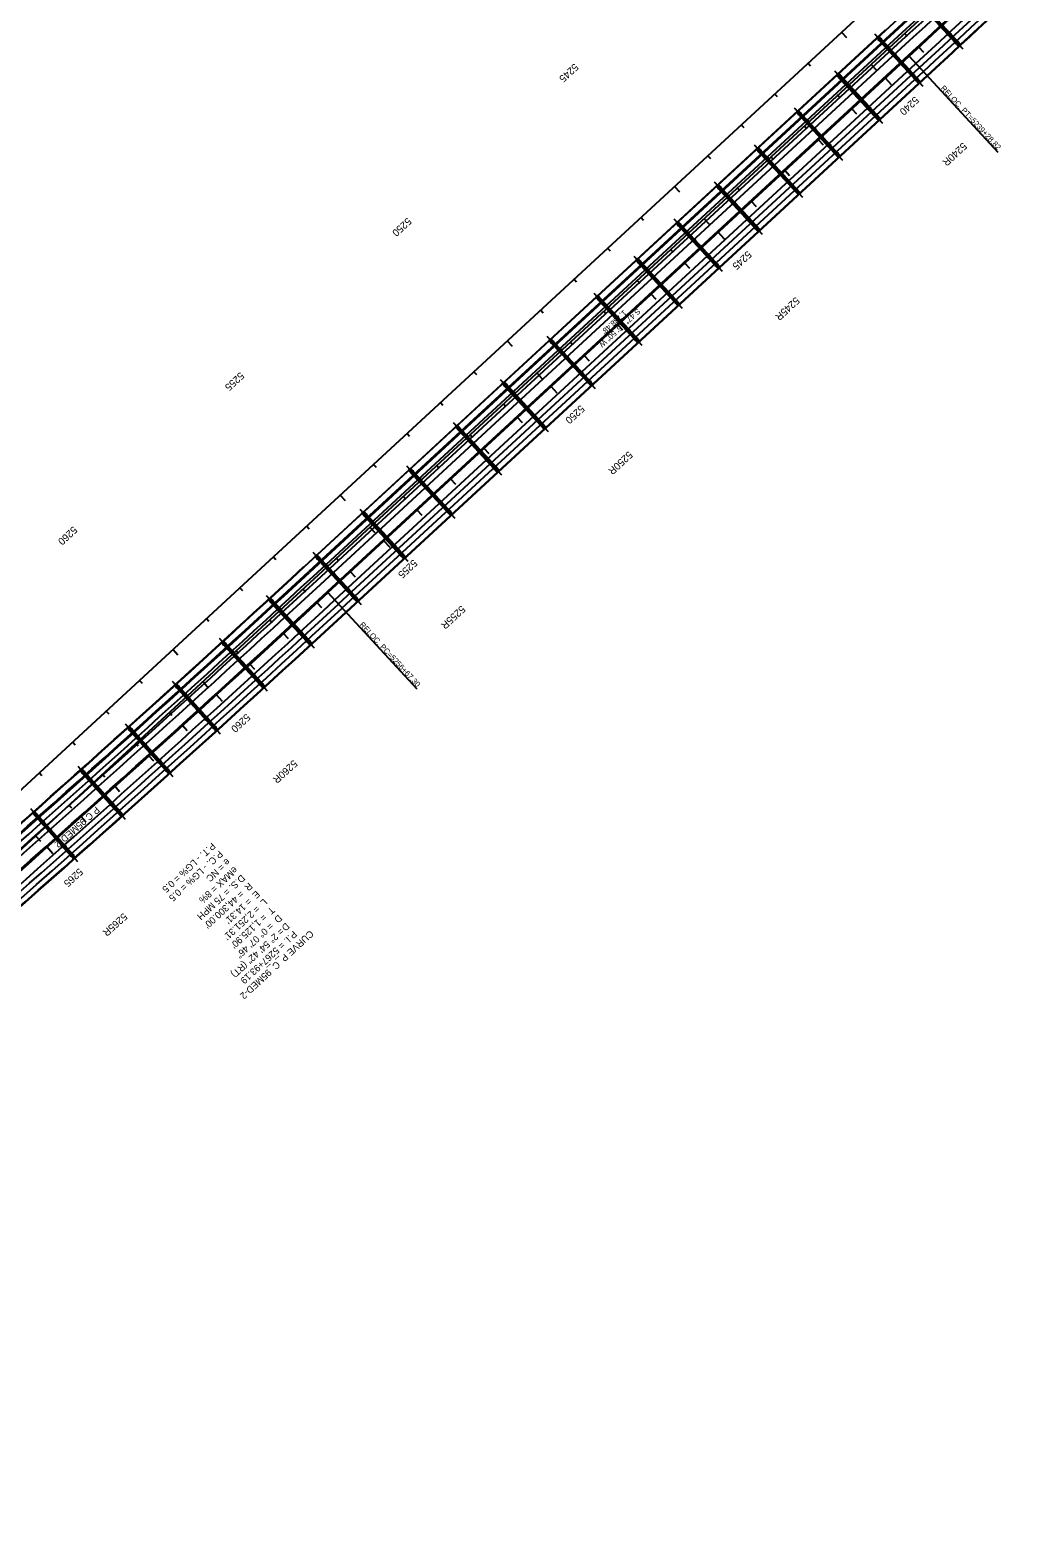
# Model space of a CAD drawing. Extents: x 2160877 to 2175861, y 601747 to 617724.
# Drawn here: x 2165397 to 2167565, y 605823 to 609138 of the extents above; entities that cross this region are included whole.
import ezdxf

# ---------------------------------------------------------------- set-up
doc = ezdxf.new("R2010")
doc.units = 0
for name, color, linetype in [('BR_CENTER LINES', 7, 'Continuous'), ('BR_CONCRETE', 7, 'Continuous'), ('RD_HC_Cl', 7, 'Continuous'), ('RD_HC_CL_Rel', 7, 'Continuous'), ('RD_HC_Data_Rel', 7, 'Continuous'), ('RD_HC_Data_Tic', 7, 'Continuous'), ('RD_HC_Data_Tic_Rel', 7, 'Continuous'), ('RD_HC_TX_Rel_Sta50', 7, 'Continuous'), ('RD_HC_TX_Rel_StaOther', 7, 'Continuous'), ('RD_HC_TX_StaOther', 7, 'Continuous'), ('RD_PD_Final_LnLine', 7, 'Continuous'), ('RD_PD_MedBWall', 7, 'Continuous')]:
    doc.layers.add(name, color=color, linetype=linetype)

msp = doc.modelspace()

# ---------------------------------------------------------------- linework, layer by layer
at = {"layer": 'BR_CENTER LINES'}
for p, q in [((2167340.3, 609210.9), (2167446.5, 609096.4)), ((2167252.3, 609129.6), (2167358.3, 609014.8)), ((2167164.1, 609048.2), (2167270.1, 608933.4)), ((2167076, 608966.8), (2167181.9, 608852)), ((2166987.8, 608885.3), (2167093.8, 608770.6)), ((2166899.7, 608803.9), (2167005.6, 608689.2)), ((2166811.5, 608722.5), (2166917.4, 608607.8)), ((2166723.3, 608641.1), (2166829.3, 608526.4)), ((2166635.2, 608559.7), (2166741.1, 608445)), ((2166532.3, 608464.7), (2166638.3, 608350)), ((2166429.5, 608369.8), (2166535.4, 608255)), ((2166326.6, 608274.8), (2166432.6, 608160)), ((2166223.8, 608179.8), (2166329.7, 608065.1)), ((2166120.9, 608084.8), (2166226.8, 607970.1)), ((2166018, 607989.8), (2166124, 607875.1)), ((2165915.2, 607895.1), (2166021, 607780.1)), ((2165812.2, 607800.7), (2165917.6, 607685.4)), ((2165708.9, 607706.6), (2165813.9, 607591)), ((2165605.3, 607612.9), (2165709.9, 607496.9)), ((2165501.3, 607519.5), (2165605.6, 607403.2)), ((2165397.1, 607426.4), (2165501, 607309.8))]:
    msp.add_line(p, q, dxfattribs=at)
at = {"layer": 'BR_CONCRETE'}
for p, q in [((2167275.8, 609137.6), (2165998.5, 607958.2)), ((2167285.9, 609126.6), (2166008.7, 607947.2)), ((2167287.5, 609124.9), (2166010.3, 607945.5)), ((2167326.9, 609082.3), (2166049.6, 607902.9)), ((2167328.4, 609080.5), (2166051.2, 607901.1)), ((2167367.8, 609037.9), (2166090.6, 607858.5)), ((2167368.5, 609037.2), (2166091.2, 607857.8)), ((2167368.6, 609037.1), (2166091.3, 607857.7))]:
    msp.add_line(p, q, dxfattribs=at)
for points in [[(2167349.1, 609205.5), (2167345.1, 609201.7), (2167437.7, 609101.8), (2167441.7, 609105.6)], [(2167261.1, 609124.1), (2167257.1, 609120.4), (2167349.5, 609020.3), (2167353.5, 609024.1)], [(2167173, 609042.7), (2167168.9, 609038.9), (2167261.3, 608938.9), (2167265.3, 608942.6)], [(2167084.8, 608961.3), (2167080.8, 608957.5), (2167173.1, 608857.5), (2167177.2, 608861.2)], [(2166996.6, 608879.9), (2166992.6, 608876.1), (2167085, 608776.1), (2167089, 608779.8)], [(2166908.5, 608798.5), (2166904.4, 608794.7), (2166996.8, 608694.7), (2167000.8, 608698.4)], [(2166820.3, 608717), (2166816.3, 608713.3), (2166908.6, 608613.3), (2166912.7, 608617)], [(2166732.1, 608635.6), (2166728.1, 608631.9), (2166820.5, 608531.9), (2166824.5, 608535.6)], [(2166644, 608554.2), (2166639.9, 608550.5), (2166732.3, 608450.5), (2166736.4, 608454.2)], [(2166541.1, 608459.2), (2166537.1, 608455.5), (2166629.5, 608355.5), (2166633.5, 608359.2)], [(2166438.3, 608364.3), (2166434.2, 608360.5), (2166526.6, 608260.5), (2166530.6, 608264.2)], [(2166335.4, 608269.3), (2166331.4, 608265.6), (2166423.8, 608165.5), (2166427.8, 608169.3)], [(2166232.6, 608174.3), (2166228.5, 608170.6), (2166320.9, 608070.5), (2166324.9, 608074.3)], [(2166129.7, 608079.3), (2166125.7, 608075.6), (2166218, 607975.6), (2166222.1, 607979.3)], [(2166026.8, 607984.4), (2166022.8, 607980.6), (2166115.2, 607880.6), (2166119.2, 607884.3)], [(2165924, 607889.6), (2165920, 607885.8), (2166012.2, 607785.6), (2166016.2, 607789.4)], [(2165821, 607795.1), (2165816.9, 607791.4), (2165908.8, 607690.9), (2165912.9, 607694.7)], [(2165717.6, 607701.1), (2165713.5, 607697.4), (2165805.1, 607596.6), (2165809.2, 607600.3)], [(2165614, 607607.3), (2165609.9, 607603.6), (2165701.1, 607502.5), (2165705.2, 607506.2)], [(2165510.1, 607513.9), (2165506, 607510.2), (2165596.9, 607408.8), (2165601, 607412.5)], [(2165405.8, 607420.8), (2165401.7, 607417.1), (2165492.3, 607315.4), (2165496.4, 607319.1)]]:
    msp.add_lwpolyline(points, close=True, dxfattribs=at)
for centre, radius in [((2167264.1, 609116.8), 3), ((2167264.1, 609116.8), 2), ((2167417, 609128.2), 3), ((2167417, 609128.2), 2), ((2167434, 609109.8), 3), ((2167434, 609109.8), 2), ((2167280, 609099.6), 3), ((2167280, 609099.6), 2), ((2167296, 609082.3), 3), ((2167296, 609082.3), 2), ((2167311.9, 609065), 3), ((2167311.9, 609065), 2), ((2167328.9, 609046.7), 3), ((2167328.9, 609046.7), 2), ((2167175.9, 609035.4), 3), ((2167175.9, 609035.4), 2), ((2167191.9, 609018.2), 3), ((2167191.9, 609018.2), 2), ((2167345.8, 609028.3), 3), ((2167345.8, 609028.3), 2), ((2167207.8, 609000.9), 3), ((2167207.8, 609000.9), 2), ((2167223.7, 608983.6), 3), ((2167223.7, 608983.6), 2), ((2167087.7, 608954), 3), ((2167087.7, 608954), 2), ((2167103.7, 608936.8), 3), ((2167240.7, 608965.3), 3), ((2167240.7, 608965.3), 2), ((2167257.7, 608946.9), 3), ((2167257.7, 608946.9), 2), ((2167103.7, 608936.8), 2), ((2167119.6, 608919.5), 3), ((2167119.6, 608919.5), 2), ((2166999.6, 608872.6), 3), ((2166999.6, 608872.6), 2), ((2167135.6, 608902.2), 3), ((2167135.6, 608902.2), 2), ((2167152.5, 608883.9), 3), ((2167152.5, 608883.9), 2), ((2167015.5, 608855.3), 3), ((2167015.5, 608855.3), 2), ((2167031.5, 608838.1), 3), ((2167169.5, 608865.5), 3), ((2167169.5, 608865.5), 2), ((2167031.5, 608838.1), 2), ((2167047.4, 608820.8), 3), ((2167047.4, 608820.8), 2), ((2166911.4, 608791.2), 3), ((2166911.4, 608791.2), 2), ((2166927.4, 608773.9), 3), ((2166927.4, 608773.9), 2), ((2167064.4, 608802.4), 3), ((2167064.4, 608802.4), 2), ((2167081.3, 608784.1), 3), ((2167081.3, 608784.1), 2), ((2166943.3, 608756.7), 3), ((2166943.3, 608756.7), 2), ((2166959.3, 608739.4), 3), ((2166959.3, 608739.4), 2), ((2166823.3, 608709.8), 3), ((2166823.3, 608709.8), 2), ((2166976.2, 608721), 3), ((2166976.2, 608721), 2), ((2166839.2, 608692.5), 3), ((2166839.2, 608692.5), 2), ((2166855.1, 608675.3), 3), ((2166855.1, 608675.3), 2), ((2166993.2, 608702.7), 3), ((2166993.2, 608702.7), 2), ((2166871.1, 608658), 3), ((2166871.1, 608658), 2), ((2166888, 608639.6), 3), ((2166888, 608639.6), 2), ((2166735.1, 608628.4), 3), ((2166735.1, 608628.4), 2), ((2166751, 608611.1), 3), ((2166751, 608611.1), 2), ((2166905, 608621.3), 3), ((2166905, 608621.3), 2), ((2166767, 608593.9), 3), ((2166767, 608593.9), 2), ((2166782.9, 608576.6), 3), ((2166782.9, 608576.6), 2), ((2166646.9, 608547), 3), ((2166646.9, 608547), 2), ((2166799.9, 608558.2), 3), ((2166799.9, 608558.2), 2), ((2166816.8, 608539.9), 3), ((2166662.9, 608529.7), 3), ((2166662.9, 608529.7), 2), ((2166678.8, 608512.4), 3), ((2166678.8, 608512.4), 2), ((2166816.8, 608539.9), 2), ((2166694.8, 608495.2), 3), ((2166694.8, 608495.2), 2), ((2166711.7, 608476.8), 3), ((2166711.7, 608476.8), 2), ((2166544.1, 608452), 3), ((2166544.1, 608452), 2), ((2166728.7, 608458.4), 3), ((2166728.7, 608458.4), 2), ((2166560, 608434.7), 3), ((2166560, 608434.7), 2), ((2166576, 608417.5), 3), ((2166576, 608417.5), 2), ((2166591.9, 608400.2), 3), ((2166591.9, 608400.2), 2), ((2166608.9, 608381.8), 3), ((2166608.9, 608381.8), 2), ((2166441.2, 608357), 3), ((2166441.2, 608357), 2), ((2166625.8, 608363.5), 3), ((2166625.8, 608363.5), 2), ((2166457.2, 608339.8), 3), ((2166457.2, 608339.8), 2), ((2166473.1, 608322.5), 3), ((2166473.1, 608322.5), 2), ((2166489.1, 608305.2), 3), ((2166489.1, 608305.2), 2), ((2166506, 608286.9), 3), ((2166506, 608286.9), 2), ((2166338.4, 608262), 3), ((2166338.4, 608262), 2), ((2166354.3, 608244.8), 3), ((2166354.3, 608244.8), 2), ((2166523, 608268.5), 3), ((2166523, 608268.5), 2), ((2166370.3, 608227.5), 3), ((2166370.3, 608227.5), 2), ((2166386.2, 608210.2), 3), ((2166386.2, 608210.2), 2), ((2166403.2, 608191.9), 3), ((2166403.2, 608191.9), 2), ((2166235.5, 608167.1), 3), ((2166235.5, 608167.1), 2), ((2166251.5, 608149.8), 3), ((2166251.5, 608149.8), 2), ((2166420.1, 608173.5), 3), ((2166420.1, 608173.5), 2), ((2166267.4, 608132.5), 3), ((2166267.4, 608132.5), 2), ((2166283.3, 608115.3), 3), ((2166283.3, 608115.3), 2), ((2166300.3, 608096.9), 3), ((2166300.3, 608096.9), 2), ((2166317.3, 608078.5), 3), ((2166317.3, 608078.5), 2), ((2166132.7, 608072.1), 3), ((2166132.7, 608072.1), 2), ((2166148.6, 608054.8), 3), ((2166148.6, 608054.8), 2), ((2166164.5, 608037.6), 3), ((2166164.5, 608037.6), 2), ((2166180.5, 608020.3), 3), ((2166180.5, 608020.3), 2), ((2166029.8, 607977.1), 3), ((2166029.8, 607977.1), 2), ((2166197.4, 608001.9), 3), ((2166197.4, 608001.9), 2), ((2166214.4, 607983.6), 3), ((2166214.4, 607983.6), 2), ((2166045.7, 607959.8), 3), ((2166045.7, 607959.8), 2), ((2166061.7, 607942.6), 3), ((2166061.7, 607942.6), 2), ((2166077.6, 607925.3), 3), ((2166077.6, 607925.3), 2), ((2165926.9, 607882.3), 3), ((2165926.9, 607882.3), 2), ((2166094.6, 607906.9), 3), ((2166094.6, 607906.9), 2), ((2166111.6, 607888.6), 3), ((2166111.6, 607888.6), 2), ((2165942.9, 607865), 3), ((2165942.9, 607865), 2), ((2165958.8, 607847.7), 3), ((2165958.8, 607847.7), 2), ((2165974.7, 607830.4), 3), ((2165974.7, 607830.4), 2), ((2165991.6, 607812), 3), ((2165991.6, 607812), 2), ((2165823.9, 607787.9), 3), ((2165823.9, 607787.9), 2), ((2166008.5, 607793.6), 3), ((2166008.5, 607793.6), 2), ((2165839.7, 607770.5), 3), ((2165839.7, 607770.5), 2), ((2165855.6, 607753.2), 3), ((2165855.6, 607753.2), 2), ((2165871.5, 607735.8), 3), ((2165871.5, 607735.8), 2), ((2165888.3, 607717.4), 3), ((2165888.3, 607717.4), 2), ((2165720.5, 607693.8), 3), ((2165720.5, 607693.8), 2), ((2165905.2, 607699), 3), ((2165905.2, 607699), 2), ((2165736.3, 607676.4), 3), ((2165736.3, 607676.4), 2), ((2165752.1, 607659), 3), ((2165752.1, 607659), 2), ((2165767.9, 607641.6), 3), ((2165767.9, 607641.6), 2), ((2165784.7, 607623.1), 3), ((2165784.7, 607623.1), 2), ((2165616.9, 607600), 3), ((2165616.9, 607600), 2), ((2165632.6, 607582.6), 3), ((2165632.6, 607582.6), 2), ((2165801.6, 607604.6), 3), ((2165801.6, 607604.6), 2), ((2165648.4, 607565.1), 3), ((2165648.4, 607565.1), 2), ((2165664.1, 607547.7), 3), ((2165664.1, 607547.7), 2), ((2165680.8, 607529.1), 3), ((2165680.8, 607529.1), 2), ((2165512.9, 607506.6), 3), ((2165512.9, 607506.6), 2), ((2165528.6, 607489.1), 3), ((2165528.6, 607489.1), 2), ((2165697.6, 607510.6), 3), ((2165697.6, 607510.6), 2), ((2165544.3, 607471.6), 3), ((2165544.3, 607471.6), 2), ((2165560, 607454.1), 3), ((2165560, 607454.1), 2), ((2165408.7, 607413.5), 3), ((2165408.7, 607413.5), 2), ((2165576.7, 607435.5), 3), ((2165576.7, 607435.5), 2), ((2165593.4, 607416.9), 3), ((2165593.4, 607416.9), 2), ((2165424.3, 607395.9), 3), ((2165424.3, 607395.9), 2), ((2165439.9, 607378.4), 3), ((2165439.9, 607378.4), 2), ((2165455.6, 607360.8), 3), ((2165455.6, 607360.8), 2), ((2165472.2, 607342.2), 3), ((2165472.2, 607342.2), 2), ((2165488.8, 607323.5), 3), ((2165488.8, 607323.5), 2)]:
    msp.add_circle(centre, radius, dxfattribs=at)
for centre, radius, start, end in [((2118143, 662346), 72438.5, 312.719474, 314.001576), ((2118143, 662346), 72440.8, 312.719474, 314.001576), ((2118143, 662346), 72498.8, 312.719474, 314.001574), ((2118143, 662346), 72501.2, 312.719474, 314.001574), ((2118143, 662346), 72559.2, 312.719474, 314.001572), ((2118143, 662346), 72560.2, 312.719474, 314.001572), ((2118143, 662346), 72560.3, 312.719474, 314.001572), ((2135996.9, 640448.5), 44223.5, 311.14908, 312.71947), ((2135996.9, 640448.5), 44238.5, 311.14908, 312.71947), ((2135996.9, 640448.5), 44240.8, 311.14908, 312.71947), ((2135996.9, 640448.5), 44298.8, 311.14908, 312.71947), ((2135996.9, 640448.5), 44301.2, 311.14908, 312.71947), ((2135996.9, 640448.5), 44359.2, 311.14907, 312.71947), ((2135996.9, 640448.5), 44360.2, 311.14907, 312.71947), ((2135996.9, 640448.5), 44360.3, 311.14907, 312.71947)]:
    msp.add_arc(centre, radius, start, end, dxfattribs=at)
at = {"layer": 'RD_HC_Cl'}
for p, q in [((2172207.3, 613775.1), (2163672.2, 605893.8)), ((2172272.5, 613704.6), (2163737.4, 605823.3))]:
    msp.add_line(p, q, dxfattribs=at)
at = {"layer": 'RD_HC_CL_Rel'}
msp.add_line((2167327.7, 609081.4), (2166050.4, 607902), dxfattribs=at)
for centre, radius, start, end in [((2118143, 662346), 72500, 312.719474, 314.517591), ((2135996.9, 640448.5), 44300, 309.80773, 312.71947)]:
    msp.add_arc(centre, radius, start, end, dxfattribs=at)
at = {"layer": 'RD_HC_Data_Rel'}
for p, q in [((2167327.7, 609081.4), (2167523.3, 608869.6)), ((2166050.4, 607902), (2166246.8, 607689.4))]:
    msp.add_line(p, q, dxfattribs=at)
at = {"layer": 'RD_HC_Data_Tic'}
for p, q in [((2167180, 609132.9), (2167190.9, 609121.2)), ((2167318.6, 609130.2), (2167324.1, 609124.4)), ((2167106.6, 609065.1), (2167112, 609059.2)), ((2167245.2, 609062.4), (2167256, 609050.6)), ((2167033.1, 608997.2), (2167038.5, 608991.4)), ((2167171.7, 608994.6), (2167177.1, 608988.7)), ((2166959.6, 608929.4), (2166965.1, 608923.5)), ((2167098.2, 608926.7), (2167103.6, 608920.8)), ((2166886.2, 608861.6), (2166891.6, 608855.7)), ((2167024.8, 608858.9), (2167030.2, 608853)), ((2166812.7, 608793.7), (2166823.5, 608782)), ((2166951.3, 608791), (2166956.7, 608785.2)), ((2166739.2, 608725.9), (2166744.6, 608720)), ((2166877.8, 608723.2), (2166888.7, 608711.4)), ((2166665.7, 608658), (2166671.2, 608652.2)), ((2166804.3, 608655.3), (2166809.8, 608649.5)), ((2166592.3, 608590.2), (2166597.7, 608584.3)), ((2166730.9, 608587.5), (2166736.3, 608581.6)), ((2166518.8, 608522.4), (2166524.2, 608516.5)), ((2166657.4, 608519.7), (2166662.8, 608513.8)), ((2166445.3, 608454.5), (2166456.2, 608442.8)), ((2166583.9, 608451.8), (2166589.4, 608445.9)), ((2166371.9, 608386.7), (2166377.3, 608380.8)), ((2166510.5, 608384), (2166521.3, 608372.2)), ((2166298.4, 608318.8), (2166303.8, 608313)), ((2166437, 608316.1), (2166442.4, 608310.3)), ((2166224.9, 608251), (2166230.4, 608245.1)), ((2166363.5, 608248.3), (2166369, 608242.4)), ((2166151.5, 608183.1), (2166156.9, 608177.3)), ((2166290.1, 608180.5), (2166295.5, 608174.6)), ((2166078, 608115.3), (2166088.9, 608103.6)), ((2166216.6, 608112.6), (2166222, 608106.7)), ((2166004.5, 608047.5), (2166010, 608041.6)), ((2166143.1, 608044.8), (2166154, 608033)), ((2165931.1, 607979.6), (2165936.5, 607973.7)), ((2166069.7, 607976.9), (2166075.1, 607971.1)), ((2165857.6, 607911.8), (2165863, 607905.9)), ((2165996.2, 607909.1), (2166001.6, 607903.2)), ((2165784.1, 607843.9), (2165789.6, 607838.1)), ((2165922.7, 607841.3), (2165928.2, 607835.4)), ((2165710.7, 607776.1), (2165721.5, 607764.3)), ((2165849.3, 607773.4), (2165854.7, 607767.5)), ((2165637.2, 607708.3), (2165642.6, 607702.4)), ((2165775.8, 607705.6), (2165786.6, 607693.8)), ((2165563.7, 607640.4), (2165569.2, 607634.5)), ((2165702.3, 607637.7), (2165707.7, 607631.9)), ((2165490.3, 607572.6), (2165495.7, 607566.7)), ((2165628.9, 607569.9), (2165634.3, 607564)), ((2165416.8, 607504.7), (2165422.2, 607498.9)), ((2165555.4, 607502.1), (2165560.8, 607496.2)), ((2165481.9, 607434.2), (2165487.3, 607428.3)), ((2165408.4, 607366.4), (2165419.3, 607354.6))]:
    msp.add_line(p, q, dxfattribs=at)
at = {"layer": 'RD_HC_Data_Tic_Rel'}
for p, q in [((2167348.8, 609101), (2167359.7, 609089.2)), ((2167275.4, 609033.1), (2167288.9, 609018.4)), ((2167201.9, 608965.3), (2167212.7, 608953.5)), ((2167128.4, 608897.4), (2167139.3, 608885.7)), ((2167055, 608829.6), (2167065.8, 608817.8)), ((2166981.5, 608761.8), (2166992.3, 608750)), ((2166908, 608693.9), (2166921.6, 608679.2)), ((2166834.6, 608626.1), (2166845.4, 608614.3)), ((2166761.1, 608558.2), (2166771.9, 608546.5)), ((2166687.6, 608490.4), (2166698.5, 608478.6)), ((2166614.1, 608422.5), (2166625, 608410.8)), ((2166540.7, 608354.7), (2166554.2, 608340)), ((2166467.2, 608286.9), (2166478.1, 608275.1)), ((2166393.7, 608219), (2166404.6, 608207.3)), ((2166320.3, 608151.2), (2166331.1, 608139.4)), ((2166246.8, 608083.3), (2166257.7, 608071.6)), ((2166173.3, 608015.5), (2166186.9, 608000.8)), ((2166099.9, 607947.7), (2166110.7, 607935.9)), ((2166026.4, 607879.8), (2166037.2, 607868.1)), ((2165952.8, 607812.1), (2165963.6, 607800.3)), ((2165879, 607744.6), (2165889.8, 607732.8)), ((2165805.1, 607677.2), (2165818.6, 607662.4)), ((2165731.1, 607610), (2165741.8, 607598.2)), ((2165656.9, 607543), (2165667.6, 607531.1)), ((2165582.5, 607476.1), (2165593.2, 607464.2)), ((2165508, 607409.4), (2165518.7, 607397.5)), ((2165433.4, 607342.9), (2165446.7, 607327.9))]:
    msp.add_line(p, q, dxfattribs=at)
at = {"layer": 'RD_PD_Final_LnLine'}
for p, q in [((2166018.4, 607936.7), (2167295.7, 609116.1)), ((2166026.6, 607927.8), (2167303.8, 609107.2)), ((2166034.7, 607919), (2167311.9, 609098.4)), ((2166049.6, 607902.9), (2167326.9, 609082.3)), ((2166051.2, 607901.1), (2167328.4, 609080.5)), ((2166066.1, 607885), (2167343.4, 609064.4)), ((2166074.3, 607876.2), (2167351.5, 609055.6)), ((2166082.4, 607867.4), (2167359.7, 609046.8))]:
    msp.add_line(p, q, dxfattribs=at)
for centre, radius, start, end in [((2118143, 662346), 72452.8, 312.719474, 314.517591), ((2118143, 662346), 72464.8, 312.719474, 314.517591), ((2118143, 662346), 72476.8, 312.719474, 314.517591), ((2118143, 662346), 72498.8, 312.719474, 314.517591), ((2118143, 662346), 72501.2, 312.719474, 314.517591), ((2118143, 662346), 72523.2, 312.719474, 314.517591), ((2118143, 662346), 72535.2, 312.719474, 314.517591), ((2118143, 662346), 72547.2, 312.719474, 314.517591), ((2135996.9, 640448.5), 44252.8, 309.80773, 312.71947), ((2135996.9, 640448.5), 44264.8, 309.80773, 312.71947), ((2135996.9, 640448.5), 44276.8, 309.80773, 312.71947), ((2135996.9, 640448.5), 44298.8, 309.80773, 312.71947), ((2135996.9, 640448.5), 44301.2, 309.80773, 312.71947), ((2135996.9, 640448.5), 44323.2, 309.80773, 312.71947), ((2135996.9, 640448.5), 44335.2, 309.80773, 312.71947), ((2135996.9, 640448.5), 44347.2, 310.84704, 312.71947)]:
    msp.add_arc(centre, radius, start, end, dxfattribs=at)
at = {"layer": 'RD_PD_MedBWall'}
for p, q in [((2165998.5, 607958.2), (2167275.8, 609137.6)), ((2165999.2, 607957.5), (2167276.4, 609136.9))]:
    msp.add_line(p, q, dxfattribs=at)
for centre, radius, start, end in [((2118142.8, 662346.1), 72424.7, 312.719474, 314.001577), ((2135996.7, 640448.7), 44223.7, 311.16011, 312.71947), ((2135996.7, 640448.7), 44224.7, 311.16011, 312.71947)]:
    msp.add_arc(centre, radius, start, end, dxfattribs=at)

# ---------------------------------------------------------------- texts
at = {"layer": 'RD_HC_Data_Rel'}
for s, height, rotation, p in [('RELOC. PT=5239+28.82', 12, 312.7195, (2167397, 609009.3)), ('RELOC. PC=5256+67.30', 12, 312.7195, (2166119.7, 607829.9)), ('P C 95MED-2', 15, 221.4251, (2165541.4, 607432)), ('P.T. - LG% = 0.5', 15, 222.7195, (2165795.6, 607352.8)), ('P.C. - LG% = 0.5', 15, 222.7195, (2165811.9, 607335.2)), ('eMAX = 8%', 15, 222.7195, (2165844.4, 607299.9)), ('e = NC', 15, 222.7195, (2165828.1, 607317.6)), ('D.S. = 75 MPH', 15, 222.7195, (2165860.7, 607282.3)), ("R  = 44,300.00'", 15, 222.7195, (2165877, 607264.7)), ("L  = 2,251.31'", 15, 222.7195, (2165909.6, 607229.4)), ("E  = 14.31'", 15, 222.7195, (2165893.3, 607247.1)), ("T  = 1,125.90'", 15, 222.7195, (2165925.8, 607211.8)), ('D  = 0%%d 07\' 46"', 15, 222.7195, (2165942.1, 607194.2)), ('   = 2%%d 54\' 42" (RT)', 15, 222.7195, (2165958.4, 607176.5)), ('CURVE P_C_95MED-2', 15, 222.7195, (2166011.3, 607160)), ('P.I. = 5267+93.19', 15, 222.7195, (2165974.7, 607158.9)), ('D ', 15, 222.7195, (2165958.4, 607176.5))]:
    msp.add_text(s, height=height, rotation=rotation, dxfattribs=at).set_placement(p)
at = {"layer": 'RD_HC_TX_Rel_Sta50'}
for s, rotation, p in [('5240R', 222.7195, (2167446.5, 608891.7)), ('5245R', 222.7195, (2167078.9, 608552.2)), ('5250R', 222.7195, (2166711.8, 608213.2)), ('5255R', 222.7195, (2166344.2, 607873.8)), ('5260R', 222.2892, (2165975.2, 607534.5)), ('5265R', 221.6425, (2165601.6, 607198))]:
    msp.add_text(s, height=16, rotation=rotation, dxfattribs=at).set_placement(p)
at = {"layer": 'RD_HC_TX_Rel_StaOther'}
for s, p in [('S 47%%d 16\' 50" W', (2166731.3, 608526.6)), ("1,738.48'", (2166700.9, 608523))]:
    msp.add_text(s, height=12, rotation=222.7195, dxfattribs=at).set_placement(p)
at = {"layer": 'RD_HC_TX_StaOther'}
for s, p in [('5245', (2166592.8, 609065.5)), ('5240', (2167341, 608993)), ('5250', (2166225.8, 608726.6)), ('5245', (2166973.3, 608653.5)), ('5255', (2165858.1, 608387.1)), ('5250', (2166606.3, 608314.6)), ('5260', (2165491.2, 608048.2)), ('5255', (2166238.6, 607975.1)), ('5260', (2165871.6, 607636.2)), ('5265', (2165503.9, 607296.6))]:
    msp.add_text(s, height=16, rotation=222.7195, dxfattribs=at).set_placement(p)

doc.saveas('drawing.dxf')
